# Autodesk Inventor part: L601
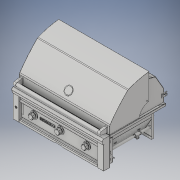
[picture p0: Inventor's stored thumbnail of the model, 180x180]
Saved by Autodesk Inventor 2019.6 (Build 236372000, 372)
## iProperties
Created: 2025-04
Part Number: L601
Material: Generic
Description: CATIA V5 STEP
Document SubType Name: Modeling
Designer: MMAK
Authority: none
Density: 1 g/cm^3
Appearance: Default
Company: none
Title: C:\Users\MMAK\Documents\SmarTeam\WEBSITE CAD\SEDONA\2025 SEDONA\L601.stp
Author: none
Revision Number: ANY
Sending System: CATIA V5 STEP AP203 v2
Preprocessor: CATIA Unofficial Packaging Version SP2
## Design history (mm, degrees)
feature "10001-2-solid1"
feature "10001-3-solid1"
feature "10001-4-solid1"
feature "11117-1-solid1"
feature "11117-2-solid1"
feature "14012-1-solid1"
feature "14012-2-solid1"
feature "14012-4-solid1"
feature "14012-5-solid1"
feature "14012-6-solid1"
feature "14012-7-solid1"
feature "14012-8-solid1"
feature "14012-9-solid1"
feature "14012-10-solid1"
feature "14012-11-solid1"
feature "14012-12-solid1"
feature "14012-14-solid1"
feature "14013-1-solid1"
feature "14013-2-solid1"
feature "81632-1_34062-1-solid1"
feature "81632-1_33767-1-solid1"
feature "81632-1_33768-1-solid1"
feature "81692-1_81627-1_37834-2-solid1"
feature "81692-1_81627-1_32769-1-solid1"
feature "81692-1_81627-1_32769-2-solid1"
feature "81692-1_81627-1_32769-3-solid1"
feature "81692-1_81627-1_32769-4-solid1"
feature "81692-1_81627-1_32769-5-solid1"
feature "81692-1_81627-1_31782-1-solid1"
feature "81692-1_81627-1_32218-3-solid1"
feature "81692-1_81627-1_32218-4-solid1"
feature "81692-1_81628-1_37837-2-solid1"
feature "81692-1_81628-1_32218-3-solid1"
feature "81692-1_81628-1_32218-4-solid1"
feature "81692-1_81628-1_31782-1-solid1"
feature "81692-1_81628-1_32769-1-solid1"
feature "81692-1_81628-1_32769-2-solid1"
feature "81692-1_81628-1_32769-3-solid1"
feature "81692-1_81628-1_32769-4-solid1"
feature "81692-1_14012-1-solid1"
feature "81692-1_14012-2-solid1"
feature "81692-1_14012-4-solid1"
feature "81692-1_14012-6-solid1"
feature "81692-1_14012-8-solid1"
feature "81692-1_14012-10-solid1"
feature "81692-1_14012-12-solid1"
feature "81692-1_14012-15-solid1"
feature "81692-1_14024-1-solid1"
feature "81692-1_14024-1-solid2"
feature "81692-1_14024-2-solid1"
feature "81692-1_14024-2-solid2"
feature "81692-1_70790-1_37801-2-solid1"
feature "81692-1_70790-1_14011-1-solid1"
feature "81700-1_70793-1_L18041-1-solid1"
feature "81700-1_70793-1_33763-1-solid1"
feature "81700-1_70793-1_37975-1-solid1"
feature "81700-1_32218-1-solid1"
feature "81700-1_32218-2-solid1"
feature "80733-1_80702-1_34073-1-solid1"
feature "80733-1_80702-1_34073-1-solid2"
feature "80733-1_80702-1_10041-1-solid1"
feature "80733-1_80702-1_10041-2-solid1"
feature "80733-1_13029-1-solid1"
feature "80733-1_34267-1-solid1"
feature "80733-1_34268-1-solid1"
feature "80733-1_13024-1-solid1"
feature "NONE"
feature "NONE:1"
feature "NONE:2"
feature "80733-1_13024-2-solid1"
feature "32469-1-solid1"
feature "32469-3-solid1"
feature "32469-2-solid1"
feature "32469-4-solid1"
feature "32477-1-solid1"
feature "32477-2-solid1"
feature "32554-1-solid1"
feature "32554-1-solid2"
feature "32554-2-solid1"
feature "32554-2-solid2"
feature "32554-3-solid1"
feature "32554-3-solid2"
feature "33558-1-solid1"
feature "37979-2-solid1"
feature "37980-1-solid1"
feature "38061-2-solid1"
feature "34075-1-solid1"
feature "34106-1-solid1"
feature "36967-1-solid1"
feature "36967-2-solid1"
feature "80696-1_34055-1-solid1"
feature "80696-1_34053-1-solid1"
feature "80696-1_34054-1-solid1"
feature "80696-1_14011-25-solid1"
feature "80696-1_14011-27-solid1"
feature "80696-1_14011-29-solid1"
feature "80696-1_14011-30-solid1"
feature "80696-1_14011-32-solid1"
feature "80696-1_14011-34-solid1"
feature "80696-1_30292-1-solid1"
feature "80696-1_30292-3-solid1"
feature "80696-1_31643-25-solid1"
feature "80696-1_31643-53-solid1"
feature "80696-1_30616-27-solid1"
feature "80696-1_30616-29-solid1"
feature "80696-1_30616-31-solid1"
feature "80696-1_30616-44-solid1"
feature "80696-1_30616-45-solid1"
feature "80696-1_30616-46-solid1"
feature "80696-1_30616-48-solid1"
feature "80696-1_30616-49-solid1"
feature "80696-1_30616-51-solid1"
feature "80696-1_30616-52-solid1"
feature "80696-1_30616-54-solid1"
feature "80696-1_30616-55-solid1"
feature "80696-1_14034-3-solid1"
feature "80696-1_33758-1-solid1"
feature "80696-1_33759-1-solid1"
feature "80696-1_34056-1-solid1"
feature "80696-1_14011-35-solid1"
feature "80696-1_14011-36-solid1"
feature "80696-1_14011-38-solid1"
feature "80696-1_14011-40-solid1"
feature "80696-1_14011-42-solid1"
feature "80696-1_14011-44-solid1"
feature "80696-1_14011-46-solid1"
feature "80696-1_14011-49-solid1"
feature "80696-1_14011-51-solid1"
feature "80696-1_14011-53-solid1"
feature "80696-1_14011-55-solid1"
feature "80696-1_14011-57-solid1"
feature "80696-1_14011-59-solid1"
feature "80696-1_14011-61-solid1"
feature "80696-1_14011-63-solid1"
feature "80696-1_14011-65-solid1"
feature "80696-1_32620-1-solid1"
feature "80696-1_32620-2-solid1"
feature "80696-1_32620-3-solid1"
feature "80696-1_32620-4-solid1"
feature "80696-1_32620-5-solid1"
feature "80696-1_32620-6-solid1"
feature "L20016-1-solid1"
feature "L20016-2-solid1"
feature "30417-1-solid1"
feature "31773-1-solid1"
feature "31773-2-solid1"
feature "31773-3-solid1"
feature "31930-8-solid1"
feature "31930-9-solid1"
feature "31930-10-solid1"
feature "31930-11-solid1"
feature "31930-12-solid1"
feature "31930-13-solid1"
feature "31930-14-solid1"
feature "31930-15-solid1"
feature "31930-16-solid1"
feature "31930-17-solid1"
feature "37846-1-solid1"
feature "37845-1-solid1"
feature "32470-1-solid1"
feature "32470-2-solid1"
body "Solid1"
body "Solid2"
body "Solid3"
body "Solid4"
body "Solid5"
body "Solid6"
body "Solid7"
body "Solid8"
body "Solid9"
body "Solid10"
body "Solid11"
body "Solid12"
body "Solid13"
body "Solid14"
body "Solid15"
body "Solid16"
body "Solid17"
body "Solid18"
body "Solid19"
body "Solid20"
body "Solid21"
body "Solid22"
body "Solid23"
body "Solid24"
body "Solid25"
body "Solid26"
body "Solid27"
body "Solid28"
body "Solid29"
body "Solid30"
body "Solid31"
body "Solid32"
body "Solid33"
body "Solid34"
body "Solid35"
body "Solid36"
body "Solid37"
body "Solid38"
body "Solid39"
body "Solid40"
body "Solid41"
body "Solid42"
body "Solid43"
body "Solid44"
body "Solid45"
body "Solid46"
body "Solid47"
body "Solid48"
body "Solid49"
body "Solid50"
body "Solid51"
body "Solid52"
body "Solid53"
body "Solid54"
body "Solid55"
body "Solid56"
body "Solid57"
body "Solid58"
body "Solid59"
body "Solid60"
body "Solid61"
body "Solid62"
body "Solid63"
body "Solid64"
body "Solid65"
body "Solid66"
body "Solid67"
body "Solid68"
body "Solid69"
body "Solid70"
body "Solid71"
body "Solid72"
body "Solid73"
body "Solid74"
body "Solid75"
body "Solid76"
body "Solid77"
body "Solid78"
body "Solid79"
body "Solid80"
body "Solid81"
body "Solid82"
body "Solid83"
body "Solid84"
body "Solid85"
body "Solid86"
body "Solid87"
body "Solid88"
body "Solid89"
body "Solid90"
body "Solid91"
body "Solid92"
body "Solid93"
body "Solid94"
body "Solid95"
body "Solid96"
body "Solid97"
body "Solid98"
body "Solid99"
body "Solid100"
body "Solid101"
body "Solid102"
body "Solid103"
body "Solid104"
body "Solid105"
body "Solid106"
body "Solid107"
body "Solid108"
body "Solid109"
body "Solid110"
body "Solid111"
body "Solid112"
body "Solid113"
body "Solid114"
body "Solid115"
body "Solid116"
body "Solid117"
body "Solid118"
body "Solid119"
body "Solid120"
body "Solid121"
body "Solid122"
body "Solid123"
body "Solid124"
body "Solid125"
body "Solid126"
body "Solid127"
body "Solid128"
body "Solid129"
body "Solid130"
body "Solid131"
body "Solid132"
body "Solid133"
body "Solid134"
body "Solid135"
body "Solid136"
body "Solid137"
body "Solid138"
body "Solid139"
body "Solid140"
body "Solid141"
body "Solid142"
body "Solid143"
body "Solid144"
body "Solid145"
body "Solid146"
body "Solid147"
body "Solid148"
body "Solid149"
body "Solid150"
body "Solid151"
body "Solid152"
body "Solid153"
body "Solid154"
body "Solid155"
body "Solid156"
body "Solid157"
body "Solid158"
body "Solid159"
body "Solid160"
body "Solid161"
body "Solid162"
body "Solid163"
body "Solid164"
body "Solid165"
body "Solid166"
body "Solid167"
body "Solid168"
body "Solid169"
body "Solid170"
body "Solid171"
body "Solid172"
body "Solid173"
